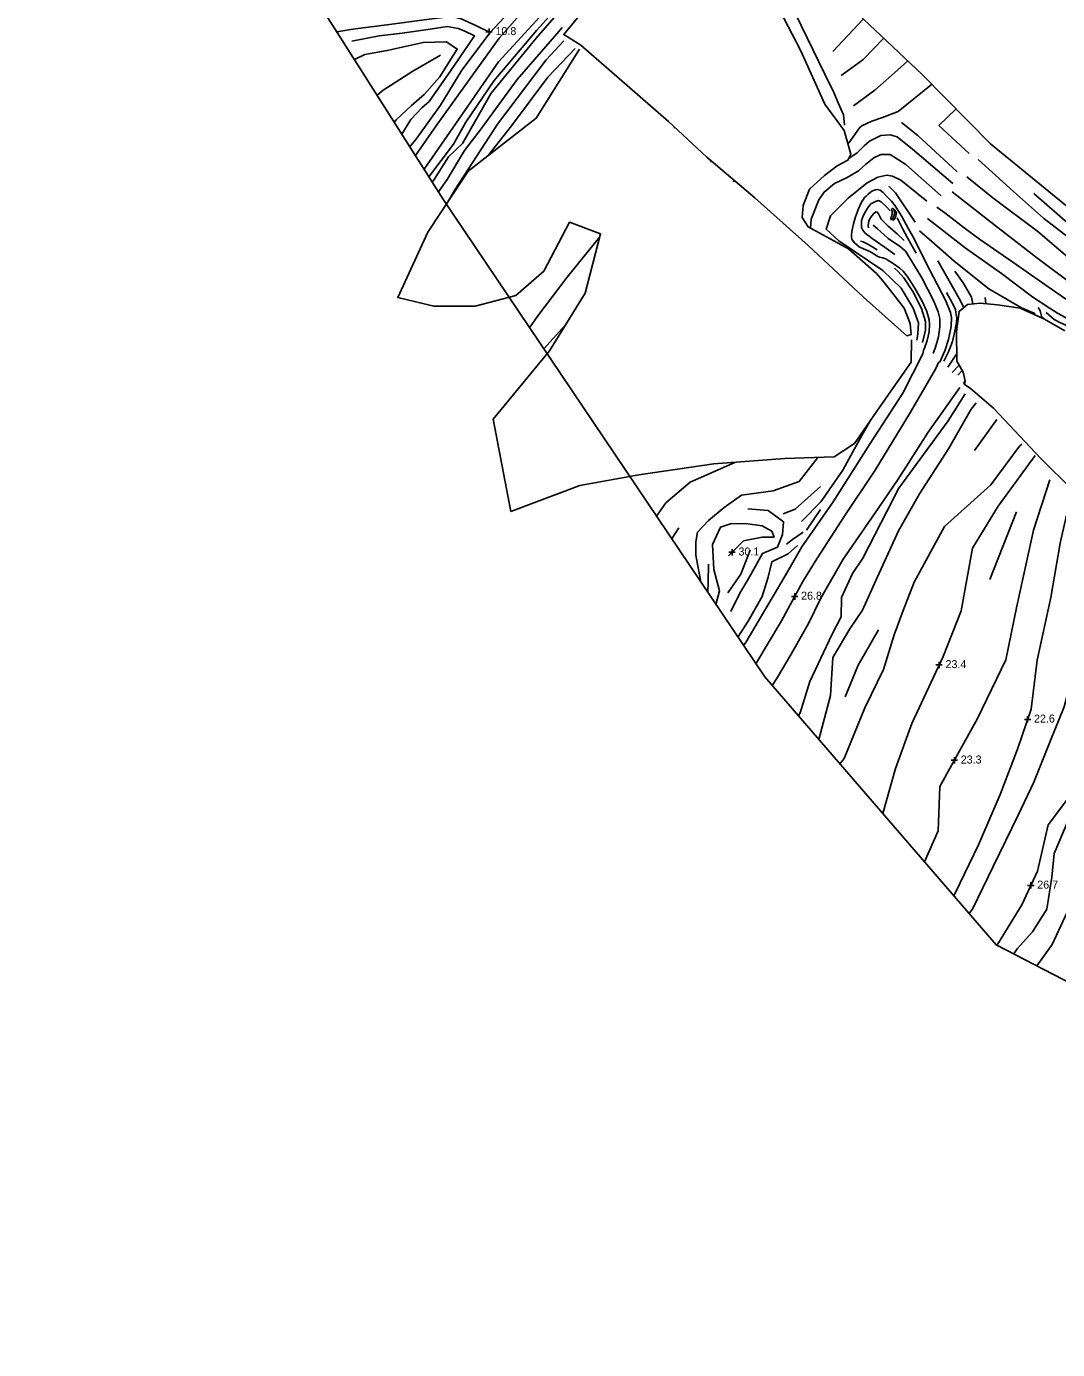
# Model space of a CAD drawing. Extents: x 2316231 to 2323598, y 363169 to 371906.
# Drawn here: x 2318772 to 2319417, y 365317 to 366144 of the extents above; entities that cross this region are included whole.
import ezdxf

# ---------------------------------------------------------------- set-up
doc = ezdxf.new("R2010")
doc.units = 0
for name, color, linetype in [('RD_DTM_BkLn1', 7, 'Continuous'), ('RD_DTM_BkLn2', 7, 'Continuous'), ('RD_DTM_Holes', 7, 'Continuous'), ('RD_DTM_TinHull', 7, 'Continuous'), ('RD_DTM_Void', 7, 'Continuous'), ('RD_EX_H2O', 7, 'Continuous'), ('RD_EX_Road', 7, 'Continuous')]:
    doc.layers.add(name, color=color, linetype=linetype)

msp = doc.modelspace()

# ---------------------------------------------------------------- linework, layer by layer
at = {"layer": 'RD_DTM_BkLn1'}
for p, q in [((2319276.67, 366128.397), (2319295.748, 366148.783)), ((2319256.667, 366129.312), (2319256.358, 366129.133)), ((2319265.261, 366109.528), (2319265.372, 366109.578)), ((2319163.413, 366093.828), (2319163.026, 366093.411)), ((2319273.823, 366093.26), (2319273.369, 366093.128)), ((2319177.829, 366081.046), (2319177.278, 366080.439)), ((2319200.142, 366059.179), (2319200.702, 366059.894)), ((2319214.907, 366047.844), (2319214.368, 366046.824)), ((2319109.474, 365957.51), (2319095.911, 365942.585)), ((2319323.725, 365950.38), (2319323.622, 365950.918)), ((2319354.073, 365939.31), (2319348.521, 365931.11)), ((2319351.264, 365927.862), (2319355.608, 365932.305)), ((2319357.506, 365929.089), (2319354.896, 365926.026)), ((2319358.302, 365920.85), (2319359.442, 365922.453)), ((2319260.254, 365829.323), (2319268.887, 365842.175)), ((2319374.904, 365798.31), (2319391.496, 365840.755)), ((2319248.727, 365814.368), (2319254.467, 365819.671))]:
    msp.add_line(p, q, dxfattribs=at)
for points in [[(2319243.932, 366171.566), (2319256.876, 366144.565), (2319271.556, 366114.268), (2319277.283, 366102.841), (2319279.917, 366096.377), (2319283.302, 366088.799), (2319284.019, 366082.335)], [(2319088.948, 366160.264), (2319068.014, 366136.699), (2319029.011, 366082.6), (2319015.665, 366063.303)], [(2319097.947, 366154.957), (2319067.689, 366121.87), (2319037.124, 366078.021), (2319021.079, 366054.778)], [(2319099.083, 366150.022), (2319091.659, 366141.721), (2319064.812, 366110.348), (2319047.177, 366084.244), (2319039.429, 366070.422), (2319024.133, 366049.97)], [(2318975.849, 366134.76), (2318992.994, 366138.212), (2319007.443, 366139.748), (2319024.771, 366142.385), (2319035.549, 366143.906), (2319042.461, 366142.707), (2319046.218, 366141.254), (2319052.578, 366138.254), (2319049.066, 366132.891), (2319037.719, 366116.538), (2319024.211, 366097.155), (2319019.636, 366093.157), (2319012.859, 366085.791), (2319007.153, 366076.705)], [(2319030.086, 366040.596), (2319035.46, 366048.329), (2319046.368, 366066.589), (2319056.193, 366079.162), (2319079.294, 366110.963), (2319104.108, 366139.332), (2319107.447, 366143.475)], [(2319002.384, 366084.215), (2319003.524, 366085.613), (2319013.107, 366094.535), (2319021.114, 366101.401), (2319030.918, 366112.575), (2319036.801, 366121.902), (2319041.847, 366129.926), (2319035.005, 366134.448), (2319020.534, 366133.903), (2318997.926, 366129.008), (2318984.035, 366126.511), (2318977.524, 366123.358)], [(2319108.361, 366134.998), (2319097.466, 366123.26), (2319066.888, 366082.99), (2319040.763, 366042.637), (2319034.979, 366033.047)], [(2319308.582, 366136.677), (2319295.363, 366123.243), (2319288.548, 366118.171), (2319281.945, 366113.325)], [(2319031.292, 366125.994), (2319014.038, 366116.178), (2318995.512, 366104.238), (2318991.664, 366101.092)], [(2319115.483, 366130.188), (2319098.535, 366112.315), (2319075.63, 366081.903), (2319061.197, 366063.297)], [(2319289.557, 366094.341), (2319302.838, 366104.113), (2319317.168, 366116.629), (2319323.465, 366122.637)], [(2319338.577, 366107.953), (2319338.184, 366107.562), (2319317.569, 366090.847), (2319307.793, 366087.177), (2319300.954, 366084.743), (2319294.858, 366081.902), (2319293.32, 366080.712), (2319289.456, 366074.959), (2319286.87, 366071.449), (2319286.005, 366071.05)], [(2319361.909, 366064.554), (2319342.949, 366082.024), (2319353.81, 366092.495)], [(2319354.374, 366053.24), (2319329.826, 366075.802), (2319319.647, 366084.082)], [(2319286.633, 366061.546), (2319291.853, 366064.992), (2319296.335, 366069.343), (2319299.589, 366072.366), (2319306.597, 366075.874), (2319312.564, 366076.22), (2319316.887, 366074.941), (2319326.55, 366067.281), (2319351.694, 366045.955)], [(2319344.323, 366038.226), (2319322.303, 366057.738), (2319312.541, 366064.107), (2319306.772, 366063.986), (2319302.213, 366061.911), (2319297.08, 366057.758), (2319292.791, 366053.76), (2319285.665, 366049.54), (2319277.738, 366045.783), (2319271.142, 366040.505), (2319267.816, 366035.62), (2319263.157, 366023.572), (2319262.606, 366017.971)], [(2319502.449, 365945.713), (2319493.491, 365945.898), (2319488.407, 365945.425), (2319482.946, 365945.588), (2319478.379, 365948.989), (2319476.202, 365952.845), (2319472.707, 365956.943), (2319467.631, 365962.512), (2319465.327, 365965.776), (2319461.875, 365974.75), (2319458.169, 365980.588), (2319451.295, 365987.543), (2319445.538, 365993.732), (2319438.463, 366000.177), (2319429.227, 366008.072), (2319408.476, 366024.276), (2319389.528, 366040.92), (2319367.629, 366060.882)], [(2319307.904, 365991.513), (2319280.497, 366010.124), (2319272.417, 366017.413), (2319275.14, 366025.766), (2319286.244, 366036.754), (2319298.183, 366046.262), (2319304.76, 366049.763), (2319310.486, 366051.17), (2319313.935, 366050.421), (2319319.137, 366048.032), (2319335.465, 366034.819)], [(2319493.415, 365932.05), (2319486.388, 365929.028), (2319482.25, 365928.808), (2319477.046, 365935.752), (2319470.367, 365945.339), (2319465.322, 365953.966), (2319462.651, 365957.584), (2319460.727, 365962.461), (2319458.645, 365965.655), (2319451.006, 365973.608), (2319433.618, 365991.327), (2319404.788, 366015.907), (2319376.655, 366036.875), (2319360.386, 366050.042)], [(2319328.139, 366021.679), (2319315.849, 366040.084), (2319311.641, 366044.296)], [(2319315.508, 366001.479), (2319308.755, 366006.264), (2319303.909, 366009.69), (2319301.32, 366011.579), (2319299.386, 366012.937), (2319297.967, 366013.922), (2319296.6, 366015.023), (2319295.32, 366016.714), (2319294.625, 366018.474), (2319294.565, 366022.653), (2319295.767, 366026.089), (2319298.353, 366030.462), (2319300.43, 366033.092), (2319303.306, 366034.716), (2319305.277, 366035.213), (2319306.844, 366034.472), (2319309.909, 366031.44), (2319312.48, 366028.787)], [(2319351.189, 366040.611), (2319378.083, 366019.676), (2319403.988, 365999.646), (2319428.751, 365981.104), (2319445.878, 365966.29), (2319453.344, 365959.208), (2319460.145, 365950.355), (2319471.162, 365935.462), (2319478.358, 365925.681), (2319481.205, 365923.456)], [(2319462.988, 365986.816), (2319455.14, 365994.319), (2319449.179, 366000.288), (2319441.755, 366006.211), (2319425.032, 366019.801), (2319402.399, 366039.722)], [(2319321.173, 366010.298), (2319316.783, 366014.433), (2319311.356, 366019.17), (2319306.791, 366023.688), (2319305.304, 366026.929), (2319304.42, 366028.003), (2319303.637, 366028.133), (2319302.21, 366027.208), (2319301.073, 366025.657), (2319300.216, 366024.404), (2319299.311, 366022.881), (2319298.888, 366021.566), (2319298.747, 366019.191), (2319298.87, 366018.268)], [(2319313.986, 366022.844), (2319315.184, 366023.641), (2319315.714, 366024.5), (2319315.968, 366025.591), (2319316.358, 366026.418), (2319316.444, 366027.447), (2319316.094, 366028.404), (2319315.279, 366029.509), (2319314.247, 366030.338), (2319313.741, 366030.251), (2319313.356, 366029.912), (2319313.528, 366028.984), (2319313.818, 366027.918), (2319313.777, 366027.011), (2319313.578, 366025.979), (2319313.162, 366025.081), (2319313.004, 366024.283), (2319313.095, 366023.678), (2319313.392, 366023.058)], [(2319314.799, 366029.479), (2319315.268, 366027.712), (2319315.278, 366026.757), (2319315.07, 366026.007), (2319314.519, 366025.345), (2319314.284, 366024.729), (2319314.209, 366024.238), (2319314.089, 366023.583)], [(2319473.321, 365918.006), (2319463.011, 365935.465), (2319449.147, 365952.582), (2319434.797, 365964.949), (2319416.053, 365977.878), (2319389.172, 365996.712), (2319368.267, 366011.092), (2319358.841, 366018.181), (2319346.636, 366027.568), (2319341.633, 366031.102)], [(2319323.634, 366001.3), (2319322.009, 366003.626), (2319318.893, 366006.296), (2319311.249, 366011.49), (2319304.376, 366017.785), (2319301.883, 366019.776)], [(2319316.835, 366024.396), (2319320.226, 366017.731), (2319323.28, 366012.023), (2319327.197, 366005.29), (2319328.714, 366002.405)], [(2319335.922, 366023.905), (2319359.509, 366005.759), (2319382.079, 365989.543), (2319401.748, 365974.892), (2319412.035, 365968.273), (2319417.185, 365964.751), (2319424.461, 365960.783), (2319431.01, 365958.911), (2319435.506, 365957.255)], [(2319130.961, 366012.456), (2319110.439, 365987.348), (2319092.132, 365963.161), (2319087.063, 365955.721)], [(2319304.284, 366004.354), (2319300.523, 366006.819), (2319298.215, 366008.143), (2319295.585, 366009.358), (2319293.95, 366009.806)], [(2319403.155, 365964.364), (2319402.48, 365964.8), (2319394.715, 365968.228), (2319374.194, 365980.01), (2319352.459, 365997.417), (2319338.479, 366009.726), (2319330.88, 366016.372)], [(2319323.634, 366001.3), (2319332.214, 365986.886), (2319339.574, 365972.746), (2319342.531, 365965.706), (2319343.647, 365961.444), (2319343.569, 365956.368), (2319342.659, 365950.003), (2319340.775, 365943.602), (2319339.476, 365939.593)], [(2319332.816, 365946.498), (2319334.502, 365954.3), (2319334.643, 365959.605), (2319332.195, 365967.809), (2319326.662, 365978.393), (2319321.099, 365986.859), (2319317.587, 365990.836), (2319315.213, 365992.909)], [(2319342.336, 365997.561), (2319355.709, 365974.029), (2319358.515, 365968.305)], [(2319307.904, 365991.513), (2319319.364, 365980.429), (2319326.803, 365968.032), (2319330.13, 365958.763), (2319329.859, 365951.981), (2319329.273, 365948.033)], [(2319364.245, 365970.599), (2319363.389, 365974.752), (2319358.133, 365983.711), (2319352.912, 365991.15)], [(2319346.052, 365934.828), (2319349.06, 365940.675), (2319351.426, 365947.064), (2319352.999, 365953.673), (2319353.923, 365959.042), (2319354.141, 365962.198), (2319353.748, 365963.698), (2319353.325, 365967.164), (2319352.393, 365969.466), (2319347.802, 365977.67)], [(2319372.381, 365970.736), (2319372.412, 365970.988), (2319371.916, 365974.536)], [(2319408.732, 365961.214), (2319407.119, 365962.93), (2319406.327, 365966.234), (2319404.987, 365968.478)], [(2319410.032, 365965.328), (2319415.061, 365960.896), (2319418.918, 365958.892), (2319422.376, 365957.382), (2319426.82, 365956.403), (2319431.973, 365955.174), (2319433.349, 365953.894), (2319433.181, 365952.48)], [(2319356.053, 365918.337), (2319336.284, 365890.517), (2319317.566, 365860.998), (2319302.635, 365839.422), (2319283.065, 365811.156)], [(2319295.356, 365811.744), (2319317.845, 365855.372), (2319348.719, 365897.498), (2319359.407, 365914.492)], [(2319303.463, 365797.836), (2319317.792, 365828.796), (2319330.924, 365851.87), (2319348.957, 365880.04), (2319363.19, 365904.78), (2319366.217, 365908.843)], [(2319256.994, 365834.71), (2319269.247, 365846.853), (2319283.007, 365866.657), (2319294.033, 365887.028), (2319300.622, 365898.603)], [(2319379.282, 365898.367), (2319365.157, 365878.983)], [(2319394.775, 365883.007), (2319393.324, 365881.721), (2319375.367, 365857.49), (2319346.436, 365831.62), (2319327.481, 365796.773), (2319320.709, 365779.025)], [(2319215.366, 365871.592), (2319187.402, 365859.228), (2319172.196, 365846.286), (2319166.391, 365837.946)], [(2319267.213, 365874.712), (2319255.502, 365859.568), (2319239.278, 365853.887), (2319219.597, 365851.051), (2319208.603, 365843.443), (2319198.838, 365835.265), (2319192.094, 365827.993), (2319190.992, 365821.851), (2319190.89, 365813.597), (2319193.917, 365798.068), (2319193.704, 365797.396)], [(2319356.833, 365778.708), (2319363.898, 365817.895), (2319380.109, 365844.147), (2319403.141, 365875.842)], [(2319391.641, 365781.693), (2319397.847, 365809.164), (2319402.222, 365829.175), (2319412.314, 365860.666)], [(2319245.628, 365839.395), (2319253.08, 365842.42), (2319268.879, 365856.581)], [(2319413.071, 365787.111), (2319418.728, 365821.104), (2319424.538, 365845.805)], [(2319212.839, 365778.355), (2319218.537, 365789.778), (2319223.416, 365798.173), (2319228.375, 365806.721), (2319232.607, 365814.609), (2319241.971, 365818.657), (2319245.271, 365826.5), (2319245.853, 365834.444), (2319236.212, 365841.431), (2319223.532, 365842.489)], [(2319180.375, 365830.728), (2319176.13, 365824.157), (2319175.939, 365823.772)], [(2319203.576, 365782.741), (2319205.886, 365791.408), (2319202.289, 365804.553), (2319201.439, 365820.315), (2319206.503, 365831.148), (2319212.612, 365833.262), (2319222.111, 365833.29), (2319232.416, 365831.986), (2319238.524, 365828.599), (2319239.868, 365824.871), (2319232.489, 365824.947), (2319220.823, 365822.577), (2319211.478, 365813.215)], [(2319258.019, 365827.925), (2319251.375, 365823.381), (2319247.582, 365820.544)], [(2319224.928, 365816.652), (2319219.101, 365801.801), (2319210.958, 365790.131)], [(2319217.285, 365762.387), (2319223.61, 365772.31), (2319232.371, 365787.774), (2319236.175, 365799.83), (2319238.612, 365809.49), (2319248.727, 365814.368)], [(2319261.491, 365770.805), (2319269.209, 365786.809), (2319283.065, 365811.156)], [(2319281.783, 365775.043), (2319282.175, 365787.065), (2319288.87, 365802.136), (2319295.356, 365811.744)], [(2319379.146, 365569.961), (2319380.325, 365571.286), (2319394.776, 365595.147), (2319404.664, 365616.04), (2319411.231, 365645.104), (2319430.818, 365671.211), (2319439.295, 365692.957), (2319441.393, 365705.001), (2319441.64, 365715.526), (2319443.061, 365725.466), (2319447.197, 365749.648), (2319447.016, 365772.007), (2319453.816, 365811.678)], [(2319198.424, 365790.388), (2319198.708, 365796.905), (2319198.874, 365807.98)], [(2319220.873, 365757.061), (2319222.37, 365759.43), (2319246.816, 365800.608)], [(2319257.95, 365797.097), (2319244.496, 365772.649), (2319228.573, 365745.628)], [(2319303.463, 365797.836), (2319295.296, 365779.32), (2319287.343, 365767.632), (2319276.627, 365749.659), (2319275.249, 365725.996), (2319267.808, 365698.477)], [(2319437.876, 365793.622), (2319429.849, 365769.023), (2319427.99, 365744.401), (2319421.366, 365718.75), (2319412.761, 365697.791), (2319402.26, 365671.676), (2319392.507, 365651.208), (2319376.884, 365619.105), (2319364.302, 365592.797), (2319361.978, 365589.629)], [(2319389.865, 365564.414), (2319391.967, 365567.582), (2319401.51, 365578.302), (2319410.536, 365592.392), (2319413.681, 365612.454), (2319415.001, 365627.254), (2319423.776, 365647.791), (2319437.731, 365666.467), (2319447.794, 365680.513), (2319449.516, 365693.388), (2319457.343, 365716.207), (2319462.478, 365738.802), (2319467.87, 365770.274), (2319474.791, 365801.469)], [(2319413.071, 365787.111), (2319404.511, 365747.9), (2319400.578, 365717.271), (2319392.168, 365692.337), (2319381.32, 365663.958), (2319367.771, 365632.564), (2319353.134, 365602.404), (2319352.319, 365600.793)], [(2319320.709, 365779.025), (2319315.063, 365763.896), (2319308.329, 365742.068), (2319296.691, 365718.198), (2319283.769, 365686.53), (2319281.119, 365683.09)], [(2319356.833, 365778.708), (2319345.586, 365750.312), (2319326.128, 365708.4), (2319315.877, 365680.287), (2319307.874, 365652.166)], [(2319391.641, 365781.693), (2319384.759, 365748.141), (2319367.09, 365711.479), (2319343.637, 365669.09), (2319342.444, 365641.287), (2319334.009, 365621.957)], [(2319404.238, 365556.976), (2319413.785, 365570.381), (2319424.749, 365593.619), (2319434.217, 365616.024), (2319444.759, 365643.529), (2319456.351, 365668.164), (2319465.265, 365690.645), (2319471.052, 365708.435), (2319475.418, 365724.264), (2319478.587, 365738.088), (2319490.023, 365765.593), (2319493.743, 365777.434)], [(2319261.491, 365770.805), (2319250.614, 365751.676), (2319241.783, 365737.023), (2319238.683, 365732.141)], [(2319281.783, 365775.043), (2319275.943, 365763.819), (2319262.258, 365734.672), (2319256.177, 365715.054), (2319255.093, 365713.173)], [(2319284.314, 365724.976), (2319292.45, 365744.916), (2319305.243, 365766.872)]]:
    msp.add_lwpolyline(points, dxfattribs=at)
at = {"layer": 'RD_DTM_BkLn2'}
for points in [[(2319327.372, 366011.632), (2319324.058, 366017.596), (2319319.755, 366025.321), (2319315.6, 366031.989), (2319313.26, 366034.918), (2319309.962, 366038.17), (2319308.037, 366040.327), (2319306.315, 366041.692), (2319304.666, 366042.126), (2319303.311, 366042.024), (2319302.074, 366041.552), (2319301.032, 366040.994), (2319299.917, 366040.256), (2319298.686, 366039.204), (2319297.524, 366037.963), (2319296.559, 366037.195), (2319295.753, 366036.1), (2319294.621, 366034.187), (2319292.647, 366030.146), (2319290.783, 366025.096), (2319289.497, 366020.589), (2319288.535, 366015.874), (2319288.262, 366013.65), (2319288.283, 366012.37), (2319288.636, 366011.109), (2319289.343, 366009.844), (2319290.278, 366008.765), (2319293.153, 366006.32), (2319295.803, 366005.127), (2319299.416, 366003.514), (2319302.332, 366001.976), (2319304.41, 366000.552), (2319305.819, 365999.863), (2319307.979, 365999.376), (2319309.699, 365998.711), (2319311.106, 365997.873), (2319313.749, 365996.224)], [(2319343.583, 365934.215), (2319346.746, 365941.27), (2319349.054, 365948.479), (2319350.639, 365956.51), (2319350.878, 365962.038), (2319350.324, 365965.245), (2319347.1, 365972.996), (2319334.704, 365996.875), (2319327.372, 366011.632)], [(2319313.749, 365996.224), (2319318.458, 365992.976), (2319320.615, 365991.038), (2319323.119, 365987.93), (2319327.912, 365980.426), (2319332.502, 365972.25), (2319335.344, 365965.85), (2319336.827, 365960.646), (2319337.149, 365957.792), (2319336.791, 365953.222), (2319335.592, 365947.809), (2319333.692, 365942.419)]]:
    msp.add_lwpolyline(points, dxfattribs=at)
at = {"layer": 'RD_DTM_Holes'}
for points in [[(2319435.599, 366021.307), (2319375.351, 366070.635), (2319332.592, 366114.027), (2319281.236, 366162.473)], [(2319116.988, 366149.49), (2319108.365, 366138.917), (2319118.99, 366132.42), (2319173.983, 366084.645), (2319197.808, 366062.349), (2319227.844, 366036.87), (2319261.218, 366007.129), (2319295.757, 365974.814), (2319322.886, 365950.697), (2319325.616, 365951.517), (2319325.075, 365958.467), (2319321.253, 365967.909), (2319314.237, 365977.222), (2319308.013, 365984.979), (2319303.932, 365989.622), (2319286.453, 366005.044), (2319261.166, 366018.752), (2319257.475, 366024.643), (2319258.207, 366032.04), (2319262.127, 366042.258), (2319271.444, 366050.81), (2319279.4, 366056.896), (2319286.069, 366060.407), (2319287.978, 366064.262), (2319283.706, 366078.957), (2319271.618, 366095.529), (2319256.346, 366129.159), (2319243.497, 366153.949)], [(2319118.171, 366129.904), (2319091.233, 366086.749), (2319048.694, 366053.535), (2319023.432, 366015.418), (2319004.573, 365974.58), (2319027.055, 365969.124), (2319053.034, 365969.239), (2319078.352, 365975.829), (2319095.865, 365991.092), (2319112.021, 366021.632), (2319131.478, 366014.42), (2319121.697, 365977.266), (2319099.489, 365941.371), (2319064.322, 365898.512), (2319075.404, 365840.931)], [(2319421.752, 365953.716), (2319409.011, 365961.088), (2319393.82, 365967.941), (2319379.522, 365970.028), (2319368.743, 365971.096), (2319360.948, 365970.235), (2319355.583, 365965.979), (2319354.005, 365953.448), (2319354.095, 365934.87), (2319358.113, 365928.06), (2319359.471, 365922.59), (2319358.975, 365920.251), (2319362.535, 365918.059), (2319377.21, 365905.528), (2319406.783, 365874.097), (2319426.562, 365854.403)], [(2319075.404, 365840.931), (2319118.421, 365857.202), (2319155.383, 365863.818), (2319202.309, 365870.583), (2319246.647, 365874.011), (2319277.5, 365875.063), (2319290.165, 365883.469), (2319305.543, 365905.726), (2319325.602, 365934.151), (2319325.852, 365948.094)]]:
    msp.add_lwpolyline(points, dxfattribs=at)
at = {"layer": 'RD_DTM_TinHull'}
msp.add_lwpolyline([(2319975.332, 365147.552), (2319890.016, 365354.444), (2319659.535, 365424.857), (2319378.87, 365570.104), (2319234.052, 365737.494), (2319033.253, 366035.61), (2318895.931, 366251.828), (2318692.475, 366476.056)], dxfattribs=at)
at = {"layer": 'RD_DTM_Void'}
for p, q in [((2319061.704, 366138.663), (2319061.704, 366142.663)), ((2319059.704, 366140.663), (2319063.704, 366140.663)), ((2319211.665, 365815.406), (2319215.665, 365815.406)), ((2319213.665, 365813.406), (2319213.665, 365817.406)), ((2319250.821, 365787.777), (2319254.821, 365787.777)), ((2319252.821, 365785.777), (2319252.821, 365789.777)), ((2319341.12, 365745), (2319345.12, 365745)), ((2319343.12, 365743), (2319343.12, 365747)), ((2319396.46, 365710.991), (2319400.46, 365710.991)), ((2319398.46, 365708.991), (2319398.46, 365712.991)), ((2319352.656, 365683.391), (2319352.656, 365687.391)), ((2319350.656, 365685.391), (2319354.656, 365685.391)), ((2319398.484, 365607.208), (2319402.484, 365607.208)), ((2319400.484, 365605.208), (2319400.484, 365609.208))]:
    msp.add_line(p, q, dxfattribs=at)
at = {"layer": 'RD_EX_H2O'}
for p, q in [((2318976.541, 366142.285), (2318966.59, 366140.573)), ((2319027.404, 366048.456), (2319026.205, 366046.707))]:
    msp.add_line(p, q, dxfattribs=at)
for points in [[(2319085.46, 366165.295), (2319062.417, 366140.336)], [(2319062.417, 366140.336), (2319053.739, 366144.315), (2319044.334, 366148.741), (2319038.374, 366150.241), (2319024.323, 366148.558), (2318999.355, 366145.306), (2318976.541, 366142.285)], [(2319027.404, 366048.456), (2319036.35, 366062.64), (2319045.03, 366070.876), (2319063.089, 366102.253), (2319091.245, 366136.635), (2319102.479, 366149.598)], [(2319031.414, 366094.91), (2319044.699, 366116.656), (2319062.417, 366140.336)], [(2319031.414, 366094.91), (2319016.44, 366074.149), (2319012.219, 366068.728)]]:
    msp.add_lwpolyline(points, dxfattribs=at)
at = {"layer": 'RD_EX_Road'}
for points in [[(2319246.816, 365800.608), (2319257.25, 365818.872), (2319276.939, 365846.92), (2319299.933, 365883.464), (2319320.438, 365914.866), (2319332.925, 365939.483), (2319333.519, 365942.454)], [(2319343.043, 365934.471), (2319340.857, 365929.855), (2319325.281, 365902.957), (2319303.123, 365866.794), (2319284.23, 365838.382), (2319266.628, 365811.369), (2319257.95, 365797.097)]]:
    msp.add_lwpolyline(points, dxfattribs=at)

# ---------------------------------------------------------------- texts
at = {"layer": 'RD_DTM_Void'}
for s, p in [('10.8', (2319065.704, 366138.663)), ('30.1', (2319217.665, 365813.406)), ('26.8', (2319256.821, 365785.777)), ('23.4', (2319347.12, 365743)), ('22.6', (2319402.46, 365708.991)), ('23.3', (2319356.656, 365683.391)), ('26.7', (2319404.484, 365605.208))]:
    msp.add_text(s, height=5, dxfattribs=at).set_placement(p)

doc.saveas('drawing.dxf')
